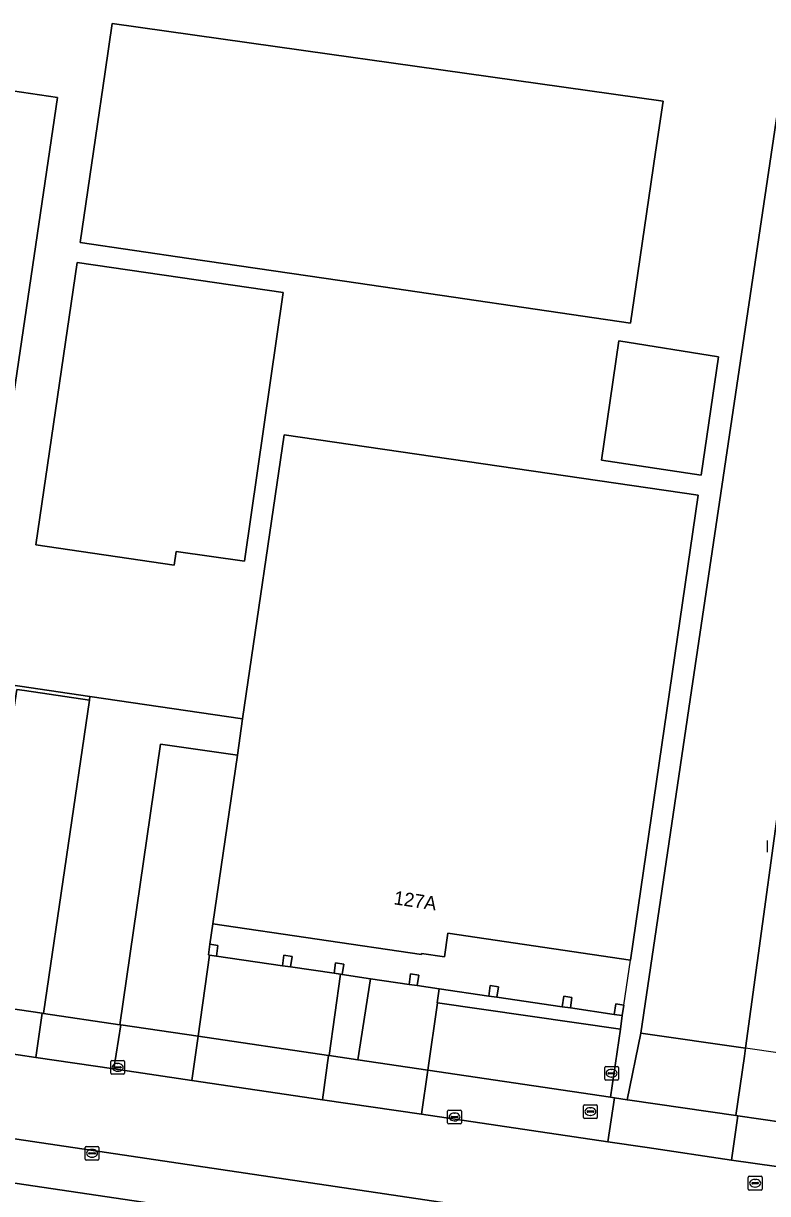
# Model space of a CAD drawing. Extents: x 163683 to 164494, y 382709 to 383872.
# Drawn here: x 163765.3 to 163819.5, y 382784.4 to 382869.7 of the extents above; entities that cross this region are included whole.
import ezdxf

# ---------------------------------------------------------------- set-up
doc = ezdxf.new("R2010")
doc.units = 0
for name, color, linetype in [('IMGEO_Brandkraan', 7, 'Continuous'), ('IMGEO_Erf', 7, 'Continuous'), ('IMGEO_Fietspad_open', 7, 'Continuous'), ('IMGEO_Groenvoorziening', 7, 'Continuous'), ('IMGEO_Hek', 7, 'Continuous'), ('IMGEO_Kolk', 7, 'Continuous'), ('IMGEO_Pand', 7, 'Continuous'), ('IMGEO_Pand_nummerreeks', 7, 'Continuous'), ('IMGEO_Pand_overbouw', 7, 'Continuous'), ('IMGEO_Parkeervlak_halfverhard', 7, 'Continuous'), ('IMGEO_Parkeervlak_open', 7, 'Continuous'), ('IMGEO_Rijbaan_lokaal_open', 7, 'Continuous'), ('IMGEO_Rioolput', 7, 'Continuous'), ('IMGEO_Voetpad_open', 7, 'Continuous')]:
    doc.layers.add(name, color=color, linetype=linetype)

msp = doc.modelspace()

# ---------------------------------------------------------------- linework, layer by layer
at = {"layer": 'IMGEO_Brandkraan'}
for p, q in [((163806.074, 382789.938), (163806.074, 382790.79)), ((163806.149, 382790.864), (163807.001, 382790.864)), ((163807.075, 382790.79), (163807.075, 382789.938)), ((163806.333, 382790.358), (163806.333, 382790.37)), ((163806.771, 382790.321), (163806.373, 382790.321)), ((163806.376, 382790.407), (163806.774, 382790.407)), ((163806.585, 382790.084), (163806.56, 382790.084)), ((163806.562, 382790.644), (163806.587, 382790.644)), ((163806.817, 382790.37), (163806.817, 382790.358)), ((163807.001, 382789.864), (163806.149, 382789.864))]:
    msp.add_line(p, q, dxfattribs=at)
for points in [[(163806.074, 382789.938), (163806.074, 382790.79)], [(163806.149, 382790.864), (163807.001, 382790.864)], [(163807.075, 382790.79), (163807.075, 382789.938)], [(163807.001, 382789.864), (163806.149, 382789.864)]]:
    msp.add_lwpolyline(points, dxfattribs=at)
for centre, radius, start, end in [((163806.151, 382790.788), 0.0765, 91.55205, 178.44795), ((163806.151, 382790.788), 0.0765, 91.55205, 178.44795), ((163806.999, 382790.788), 0.0765, 1.55205, 88.44795), ((163806.999, 382790.788), 0.0765, 1.55205, 88.44795), ((163806.151, 382789.94), 0.0765, 181.55205, 268.44795), ((163806.151, 382789.94), 0.0765, 181.55205, 268.44795), ((163806.373, 382790.367), 0.0403, 85.87752, 175.75265), ((163806.37, 382790.357), 0.0366, 178.93798, 274.71019), ((163806.774, 382790.364), 0.043, 264.86636, 352.45326), ((163806.778, 382790.369), 0.0386, 1.73085, 96.63898), ((163806.999, 382789.94), 0.0765, 271.55205, 358.44795), ((163806.999, 382789.94), 0.0765, 271.55205, 358.44795)]:
    msp.add_arc(centre, radius, start, end, dxfattribs=at)
for centre, major_axis, ratio, start_param, end_param in [((163806.561, 382790.364), (-0.387, 0.002), 0.722429, 4.712389, 7.853982), ((163806.586, 382790.364), (-0.39, 0.002), 0.717154, 1.570796, 4.712389)]:
    msp.add_ellipse(centre, major_axis=major_axis, ratio=ratio, start_param=start_param, end_param=end_param, dxfattribs=at)
at = {"layer": 'IMGEO_Erf'}
for points in [[(163771.21, 382866.138), (163771.727, 382869.661), (163787.565, 382867.423), (163792.059, 382866.788), (163811.862, 382863.99), (163811.317, 382860.283), (163810.019, 382851.453), (163809.484, 382847.817), (163789.647, 382850.729), (163777.314, 382852.539), (163769.384, 382853.703), (163770.503, 382861.322)], [(163784.189, 382850.045), (163781.367, 382830.466), (163776.389, 382831.184), (163776.246, 382830.191), (163766.152, 382831.668), (163769.164, 382852.24)], [(163815.909, 382845.374), (163814.633, 382836.729), (163807.389, 382837.829), (163808.655, 382846.518)]]:
    msp.add_lwpolyline(points, close=True, dxfattribs=at)
for points in [[(163762.015, 382821.806), (163770.099, 382820.618), (163781.231, 382818.982), (163784.247, 382839.676), (163814.425, 382835.272), (163809.484, 382801.4), (163796.175, 382803.369), (163795.929, 382801.644), (163794.274, 382801.88), (163794.263, 382801.803), (163779.053, 382804.037), (163778.839, 382802.552), (163779.434, 382802.465), (163779.328, 382801.694), (163784.13, 382800.99), (163784.241, 382801.759), (163784.837, 382801.671), (163784.727, 382800.902), (163787.888, 382800.439), (163788.002, 382801.206), (163788.604, 382801.117), (163788.484, 382800.351), (163790.544, 382800.049), (163793.36, 382799.636), (163793.471, 382800.402), (163794.069, 382800.315), (163793.952, 382799.549), (163795.545, 382799.316), (163799.167, 382798.785), (163799.277, 382799.549), (163799.877, 382799.461), (163799.764, 382798.697), (163804.514, 382798), (163804.624, 382798.764), (163805.223, 382798.676), (163805.111, 382797.913), (163808.302, 382797.445), (163808.414, 382798.207), (163809.009, 382798.119), (163808.895, 382797.358), (163808.755, 382796.374), (163808.029, 382791.413), (163808.33, 382791.369), (163809.259, 382791.231), (163810.236, 382796.066), (163813.853, 382820.4), (163821.09, 382869.088)], [(163744.772, 382867.667), (163767.747, 382864.255), (163761.467, 382821.887)]]:
    msp.add_lwpolyline(points, dxfattribs=at)
at = {"layer": 'IMGEO_Fietspad_open'}
msp.add_lwpolyline([(164145.373, 382728.607), (164025.491, 382746.53), (164025.95, 382749.729), (164024.219, 382749.984), (164023.68, 382746.794), (163989.347, 382751.871), (163943.926, 382758.588), (163798.246, 382780.157), (163792.502, 382781.012), (163764.154, 382785.228), (163700.855, 382794.642), (163698.697, 382794.967), (163698.458, 382793.117), (163700.774, 382792.768), (163796.75, 382778.554), (163938.698, 382757.534), (163989.012, 382750.084), (164063.389, 382739.07), (164145.608, 382726.742)], dxfattribs=at)
at = {"layer": 'IMGEO_Groenvoorziening'}
msp.add_lwpolyline([(163821.09, 382869.088), (163813.853, 382820.4), (163810.236, 382796.066), (163817.88, 382794.981), (163821.21, 382819.312)], dxfattribs=at)
for points in [[(163790.544, 382800.049), (163788.484, 382800.351), (163788.37, 382800.368), (163787.538, 382794.442), (163789.615, 382794.135)], [(163799.764, 382798.697), (163799.167, 382798.785), (163795.545, 382799.316), (163795.399, 382798.29), (163795.432, 382798.285), (163808.755, 382796.374), (163808.895, 382797.358), (163808.302, 382797.445), (163805.111, 382797.913), (163804.514, 382798)], [(163817.798, 382794.41), (163817.88, 382794.981), (163810.236, 382796.066), (163809.259, 382791.231), (163809.437, 382791.205), (163817.172, 382790.081)]]:
    msp.add_lwpolyline(points, close=True, dxfattribs=at)
at = {"layer": 'IMGEO_Hek'}
for points in [[(163820.406, 382794.623), (163817.88, 382794.981), (163810.236, 382796.066), (163813.853, 382820.4), (163821.09, 382869.088)], [(163810.236, 382796.066), (163809.259, 382791.231)]]:
    msp.add_lwpolyline(points, dxfattribs=at)
at = {"layer": 'IMGEO_Kolk'}
for p, q in [((163819.483, 382809.257), (163819.483, 382810.109)), ((163771.626, 382793.162), (163771.626, 382794.014)), ((163771.701, 382794.088), (163772.553, 382794.088)), ((163771.885, 382793.582), (163771.885, 382793.594)), ((163772.323, 382793.545), (163771.925, 382793.545)), ((163771.928, 382793.631), (163772.326, 382793.631)), ((163772.137, 382793.308), (163772.112, 382793.308)), ((163772.114, 382793.868), (163772.139, 382793.868)), ((163772.369, 382793.594), (163772.369, 382793.582)), ((163772.627, 382794.014), (163772.627, 382793.162)), ((163772.553, 382793.088), (163771.701, 382793.088)), ((163796.169, 382789.545), (163796.169, 382790.397)), ((163796.244, 382790.471), (163797.096, 382790.471)), ((163796.428, 382789.965), (163796.428, 382789.977)), ((163796.866, 382789.928), (163796.468, 382789.928)), ((163796.471, 382790.014), (163796.869, 382790.014)), ((163796.657, 382790.251), (163796.682, 382790.251)), ((163796.912, 382789.977), (163796.912, 382789.965)), ((163797.17, 382790.397), (163797.17, 382789.545)), ((163797.096, 382789.471), (163796.244, 382789.471)), ((163796.68, 382789.691), (163796.655, 382789.691)), ((163769.755, 382786.897), (163769.755, 382787.749)), ((163769.83, 382787.823), (163770.682, 382787.823)), ((163770.014, 382787.317), (163770.014, 382787.329)), ((163770.057, 382787.366), (163770.455, 382787.366)), ((163770.243, 382787.603), (163770.268, 382787.603)), ((163770.498, 382787.329), (163770.498, 382787.317)), ((163770.756, 382787.749), (163770.756, 382786.897)), ((163770.682, 382786.823), (163769.83, 382786.823)), ((163770.452, 382787.28), (163770.054, 382787.28)), ((163770.266, 382787.043), (163770.241, 382787.043))]:
    msp.add_line(p, q, dxfattribs=at)
for points in [[(163819.483, 382809.257), (163819.483, 382810.109)], [(163771.626, 382793.162), (163771.626, 382794.014)], [(163771.701, 382794.088), (163772.553, 382794.088)], [(163772.627, 382794.014), (163772.627, 382793.162)], [(163772.553, 382793.088), (163771.701, 382793.088)], [(163796.169, 382789.545), (163796.169, 382790.397)], [(163796.244, 382790.471), (163797.096, 382790.471)], [(163797.17, 382790.397), (163797.17, 382789.545)], [(163797.096, 382789.471), (163796.244, 382789.471)], [(163769.755, 382786.897), (163769.755, 382787.749)], [(163769.83, 382787.823), (163770.682, 382787.823)], [(163770.756, 382787.749), (163770.756, 382786.897)], [(163770.682, 382786.823), (163769.83, 382786.823)]]:
    msp.add_lwpolyline(points, dxfattribs=at)
for centre, radius, start, end in [((163771.703, 382794.012), 0.0765, 91.55205, 178.44795), ((163771.703, 382794.012), 0.0765, 91.55205, 178.44795), ((163771.925, 382793.591), 0.0403, 85.87752, 175.75265), ((163771.922, 382793.581), 0.0366, 178.93798, 274.71019), ((163772.326, 382793.588), 0.043, 264.86636, 352.45326), ((163772.33, 382793.593), 0.0386, 1.73085, 96.63898), ((163772.551, 382794.012), 0.0765, 1.55205, 88.44795), ((163772.551, 382794.012), 0.0765, 1.55205, 88.44795), ((163771.703, 382793.164), 0.0765, 181.55205, 268.44795), ((163771.703, 382793.164), 0.0765, 181.55205, 268.44795), ((163772.551, 382793.164), 0.0765, 271.55205, 358.44795), ((163772.551, 382793.164), 0.0765, 271.55205, 358.44795), ((163796.246, 382790.395), 0.0765, 91.55205, 178.44795), ((163796.246, 382790.395), 0.0765, 91.55205, 178.44795), ((163796.468, 382789.974), 0.0403, 85.87752, 175.75265), ((163796.465, 382789.964), 0.0366, 178.93798, 274.71019), ((163796.869, 382789.971), 0.043, 264.86636, 352.45326), ((163796.873, 382789.976), 0.0386, 1.73085, 96.63898), ((163797.094, 382790.395), 0.0765, 1.55205, 88.44795), ((163797.094, 382790.395), 0.0765, 1.55205, 88.44795), ((163796.246, 382789.547), 0.0765, 181.55205, 268.44795), ((163796.246, 382789.547), 0.0765, 181.55205, 268.44795), ((163797.094, 382789.547), 0.0765, 271.55205, 358.44795), ((163797.094, 382789.547), 0.0765, 271.55205, 358.44795), ((163769.832, 382787.747), 0.0765, 91.55205, 178.44795), ((163769.832, 382787.747), 0.0765, 91.55205, 178.44795), ((163770.054, 382787.326), 0.0403, 85.87752, 175.75265), ((163770.459, 382787.328), 0.0386, 1.73085, 96.63898), ((163770.68, 382787.747), 0.0765, 1.55205, 88.44795), ((163770.68, 382787.747), 0.0765, 1.55205, 88.44795), ((163769.832, 382786.899), 0.0765, 181.55205, 268.44795), ((163769.832, 382786.899), 0.0765, 181.55205, 268.44795), ((163770.051, 382787.316), 0.0366, 178.93798, 274.71019), ((163770.455, 382787.323), 0.043, 264.86636, 352.45326), ((163770.68, 382786.899), 0.0765, 271.55205, 358.44795), ((163770.68, 382786.899), 0.0765, 271.55205, 358.44795)]:
    msp.add_arc(centre, radius, start, end, dxfattribs=at)
for centre, major_axis, ratio, start_param, end_param in [((163772.113, 382793.588), (-0.387, 0.002), 0.722429, 4.712389, 7.853982), ((163772.138, 382793.588), (-0.39, 0.002), 0.717154, 1.570796, 4.712389), ((163796.656, 382789.971), (-0.387, 0.002), 0.722429, 4.712389, 7.853982), ((163796.681, 382789.971), (-0.39, 0.002), 0.717154, 1.570796, 4.712389), ((163770.242, 382787.323), (-0.387, 0.002), 0.722429, 4.712389, 7.853982), ((163770.267, 382787.323), (-0.39, 0.002), 0.717154, 1.570796, 4.712389)]:
    msp.add_ellipse(centre, major_axis=major_axis, ratio=ratio, start_param=start_param, end_param=end_param, dxfattribs=at)
at = {"layer": 'IMGEO_Pand'}
for points in [[(163811.317, 382860.283), (163811.862, 382863.99), (163792.059, 382866.788), (163787.565, 382867.423), (163771.727, 382869.661), (163771.21, 382866.138), (163770.503, 382861.322), (163769.384, 382853.703), (163777.314, 382852.539), (163789.647, 382850.729), (163809.484, 382847.817), (163810.019, 382851.453)], [(163767.747, 382864.255), (163744.772, 382867.667), (163738.347, 382824.393), (163736.362, 382811.027), (163735.926, 382808.089), (163737.957, 382807.783), (163737.854, 382807.162), (163737.767, 382806.638), (163740.305, 382806.259), (163740.32, 382806.366), (163740.381, 382806.79), (163740.469, 382807.408), (163758.915, 382804.671), (163758.918, 382804.688), (163761.467, 382821.887)], [(163784.189, 382850.045), (163769.164, 382852.24), (163766.152, 382831.668), (163776.246, 382830.191), (163776.389, 382831.184), (163781.367, 382830.466)], [(163814.633, 382836.729), (163815.909, 382845.374), (163808.655, 382846.518), (163807.389, 382837.829)], [(163814.425, 382835.272), (163784.247, 382839.676), (163781.231, 382818.982), (163780.845, 382816.332), (163779.053, 382804.037), (163794.263, 382801.803), (163794.274, 382801.88), (163795.929, 382801.644), (163796.175, 382803.369), (163809.484, 382801.4)], [(163779.434, 382802.465), (163778.839, 382802.552), (163778.731, 382801.782), (163778.816, 382801.769), (163779.328, 382801.694)], [(163784.837, 382801.671), (163784.241, 382801.759), (163784.13, 382800.99), (163784.727, 382800.902)], [(163788.604, 382801.117), (163788.002, 382801.206), (163787.888, 382800.439), (163788.37, 382800.368), (163788.484, 382800.351)], [(163794.069, 382800.315), (163793.471, 382800.402), (163793.36, 382799.636), (163793.952, 382799.549)], [(163799.877, 382799.461), (163799.277, 382799.549), (163799.167, 382798.785), (163799.764, 382798.697)], [(163805.223, 382798.676), (163804.624, 382798.764), (163804.514, 382798), (163805.111, 382797.913)], [(163809.009, 382798.119), (163808.414, 382798.207), (163808.302, 382797.445), (163808.895, 382797.358)]]:
    msp.add_lwpolyline(points, close=True, dxfattribs=at)
at = {"layer": 'IMGEO_Pand_overbouw'}
msp.add_lwpolyline([(163809.484, 382801.4), (163796.175, 382803.369), (163795.929, 382801.644), (163794.274, 382801.88), (163794.263, 382801.803), (163779.053, 382804.037), (163778.839, 382802.552), (163778.731, 382801.782), (163779.328, 382801.694), (163784.13, 382800.99), (163784.727, 382800.902), (163787.888, 382800.439), (163788.484, 382800.351), (163793.36, 382799.636), (163793.952, 382799.549), (163795.545, 382799.316), (163799.167, 382798.785), (163799.764, 382798.697), (163804.514, 382798), (163805.111, 382797.913), (163808.302, 382797.445), (163808.895, 382797.358), (163809.009, 382798.119)], close=True, dxfattribs=at)
at = {"layer": 'IMGEO_Parkeervlak_halfverhard'}
for points in [[(163770.062, 382820.356), (163765.323, 382821.046), (163764.773, 382821.126), (163761.33, 382798.315), (163761.466, 382798.295), (163766.625, 382797.532), (163766.721, 382797.518)], [(163779.053, 382804.037), (163780.845, 382816.332), (163775.25, 382817.149), (163772.292, 382796.695), (163772.345, 382796.687), (163777.979, 382795.854), (163777.999, 382795.851), (163778.816, 382801.769), (163778.731, 382801.782), (163778.839, 382802.552)], [(163808.755, 382796.374), (163795.432, 382798.285), (163794.724, 382793.379), (163808.029, 382791.413)]]:
    msp.add_lwpolyline(points, close=True, dxfattribs=at)
at = {"layer": 'IMGEO_Parkeervlak_open'}
for points in [[(163788.37, 382800.368), (163787.888, 382800.439), (163784.727, 382800.902), (163784.13, 382800.99), (163779.328, 382801.694), (163778.816, 382801.769), (163777.999, 382795.851), (163787.496, 382794.448), (163787.538, 382794.442)], [(163795.432, 382798.285), (163795.399, 382798.29), (163795.545, 382799.316), (163793.952, 382799.549), (163793.36, 382799.636), (163790.544, 382800.049), (163789.615, 382794.135), (163794.724, 382793.379)]]:
    msp.add_lwpolyline(points, close=True, dxfattribs=at)
msp.add_lwpolyline([(163761.755, 382788.511), (163764.154, 382785.228), (163792.502, 382781.012), (163795.778, 382783.493), (163796.309, 382783.673), (163761.168, 382788.88)], dxfattribs=at)
at = {"layer": 'IMGEO_Rijbaan_lokaal_open'}
for points in [[(163894.45, 382812.566), (163821.7, 382823.151), (163821.21, 382819.312), (163817.88, 382794.981), (163817.798, 382794.41), (163817.172, 382790.081), (163817.322, 382790.057), (163822.345, 382789.326), (163822.382, 382789.566), (163823.073, 382793.995), (163822.787, 382794.039), (163822.823, 382794.271), (163822.945, 382795.064), (163824.816, 382807.214), (163825.025, 382807.182), (163825.195, 382808.517)], [(163821.846, 382786.109), (163816.848, 382786.828), (163810.705, 382787.734), (163807.847, 382788.156), (163794.266, 382790.164), (163787.046, 382791.231), (163777.535, 382792.636), (163771.854, 382793.476), (163766.172, 382794.316), (163760.998, 382795.081), (163757.401, 382795.612), (163739.118, 382798.314), (163733.089, 382799.205), (163730.997, 382799.514), (163729.55, 382799.728)], [(163701.006, 382797.795), (163761.168, 382788.88), (163796.309, 382783.673)]]:
    msp.add_lwpolyline(points, dxfattribs=at)
for points in [[(163775.25, 382817.149), (163780.845, 382816.332), (163781.231, 382818.982), (163770.099, 382820.618), (163770.062, 382820.356), (163766.721, 382797.518), (163772.292, 382796.695)], [(163822.345, 382789.326), (163817.322, 382790.057), (163816.848, 382786.828), (163821.846, 382786.109)]]:
    msp.add_lwpolyline(points, close=True, dxfattribs=at)
at = {"layer": 'IMGEO_Rioolput'}
for p, q in [((163807.615, 382792.729), (163807.615, 382793.581)), ((163807.69, 382793.655), (163808.542, 382793.655)), ((163808.103, 382793.435), (163808.128, 382793.435)), ((163808.616, 382793.581), (163808.616, 382792.729)), ((163808.542, 382792.655), (163807.69, 382792.655)), ((163807.874, 382793.149), (163807.874, 382793.161)), ((163808.312, 382793.112), (163807.914, 382793.112)), ((163807.917, 382793.198), (163808.315, 382793.198)), ((163808.126, 382792.875), (163808.101, 382792.875)), ((163808.358, 382793.161), (163808.358, 382793.149)), ((163818.152, 382785.645), (163819.004, 382785.645)), ((163818.077, 382784.719), (163818.077, 382785.571)), ((163818.336, 382785.139), (163818.336, 382785.151)), ((163818.774, 382785.102), (163818.376, 382785.102)), ((163818.379, 382785.188), (163818.777, 382785.188)), ((163818.588, 382784.865), (163818.563, 382784.865)), ((163818.565, 382785.425), (163818.59, 382785.425)), ((163818.82, 382785.151), (163818.82, 382785.139)), ((163819.078, 382785.571), (163819.078, 382784.719)), ((163819.004, 382784.645), (163818.152, 382784.645))]:
    msp.add_line(p, q, dxfattribs=at)
for points in [[(163807.615, 382792.729), (163807.615, 382793.581)], [(163807.69, 382793.655), (163808.542, 382793.655)], [(163808.616, 382793.581), (163808.616, 382792.729)], [(163808.542, 382792.655), (163807.69, 382792.655)], [(163818.152, 382785.645), (163819.004, 382785.645)], [(163818.077, 382784.719), (163818.077, 382785.571)], [(163819.078, 382785.571), (163819.078, 382784.719)], [(163819.004, 382784.645), (163818.152, 382784.645)]]:
    msp.add_lwpolyline(points, dxfattribs=at)
for centre, radius, start, end in [((163807.692, 382793.579), 0.0765, 91.55205, 178.44795), ((163807.692, 382793.579), 0.0765, 91.55205, 178.44795), ((163808.54, 382793.579), 0.0765, 1.55205, 88.44795), ((163808.54, 382793.579), 0.0765, 1.55205, 88.44795), ((163807.692, 382792.731), 0.0765, 181.55205, 268.44795), ((163807.692, 382792.731), 0.0765, 181.55205, 268.44795), ((163807.914, 382793.158), 0.0403, 85.87752, 175.75265), ((163807.911, 382793.148), 0.0366, 178.93798, 274.71019), ((163808.315, 382793.155), 0.043, 264.86636, 352.45326), ((163808.319, 382793.16), 0.0386, 1.73085, 96.63898), ((163808.54, 382792.731), 0.0765, 271.55205, 358.44795), ((163808.54, 382792.731), 0.0765, 271.55205, 358.44795), ((163818.154, 382785.569), 0.0765, 91.55205, 178.44795), ((163818.154, 382785.569), 0.0765, 91.55205, 178.44795), ((163819.002, 382785.569), 0.0765, 1.55205, 88.44795), ((163819.002, 382785.569), 0.0765, 1.55205, 88.44795), ((163818.376, 382785.148), 0.0403, 85.87752, 175.75265), ((163818.373, 382785.138), 0.0366, 178.93798, 274.71019), ((163818.777, 382785.145), 0.043, 264.86636, 352.45326), ((163818.781, 382785.15), 0.0386, 1.73085, 96.63898), ((163818.154, 382784.721), 0.0765, 181.55205, 268.44795), ((163818.154, 382784.721), 0.0765, 181.55205, 268.44795), ((163819.002, 382784.721), 0.0765, 271.55205, 358.44795), ((163819.002, 382784.721), 0.0765, 271.55205, 358.44795)]:
    msp.add_arc(centre, radius, start, end, dxfattribs=at)
for centre, major_axis, ratio, start_param, end_param in [((163808.102, 382793.155), (-0.387, 0.002), 0.722429, 4.712389, 7.853982), ((163808.127, 382793.155), (-0.39, 0.002), 0.717154, 1.570796, 4.712389), ((163818.564, 382785.145), (-0.387, 0.002), 0.722429, 4.712389, 7.853982), ((163818.589, 382785.145), (-0.39, 0.002), 0.717154, 1.570796, 4.712389)]:
    msp.add_ellipse(centre, major_axis=major_axis, ratio=ratio, start_param=start_param, end_param=end_param, dxfattribs=at)
at = {"layer": 'IMGEO_Voetpad_open'}
for points in [[(163764.773, 382821.126), (163765.323, 382821.046), (163770.062, 382820.356), (163770.099, 382820.618), (163762.015, 382821.806), (163759.506, 382804.602), (163758.918, 382804.688), (163758.915, 382804.671), (163758.827, 382804.076), (163757.985, 382798.809), (163761.33, 382798.315)], [(163766.625, 382797.532), (163761.466, 382798.295), (163760.998, 382795.081), (163766.172, 382794.316)], [(163772.345, 382796.687), (163772.292, 382796.695), (163766.721, 382797.518), (163766.625, 382797.532), (163766.172, 382794.316), (163771.854, 382793.476)], [(163777.979, 382795.854), (163772.345, 382796.687), (163771.854, 382793.476), (163777.535, 382792.636)], [(163787.496, 382794.448), (163777.999, 382795.851), (163777.979, 382795.854), (163777.535, 382792.636), (163787.046, 382791.231)], [(163794.724, 382793.379), (163789.615, 382794.135), (163787.538, 382794.442), (163787.496, 382794.448), (163787.046, 382791.231), (163794.266, 382790.164)], [(163808.33, 382791.369), (163808.029, 382791.413), (163794.724, 382793.379), (163794.266, 382790.164), (163807.847, 382788.156)], [(163817.322, 382790.057), (163817.172, 382790.081), (163809.437, 382791.205), (163809.259, 382791.231), (163808.33, 382791.369), (163807.847, 382788.156), (163810.705, 382787.734), (163816.848, 382786.828)]]:
    msp.add_lwpolyline(points, close=True, dxfattribs=at)

# ---------------------------------------------------------------- texts
at = {"layer": 'IMGEO_Pand_nummerreeks'}
msp.add_text('127A', height=1, rotation=351.58325, dxfattribs=at).set_placement((163792.195, 382805.474))

doc.saveas('drawing.dxf')
